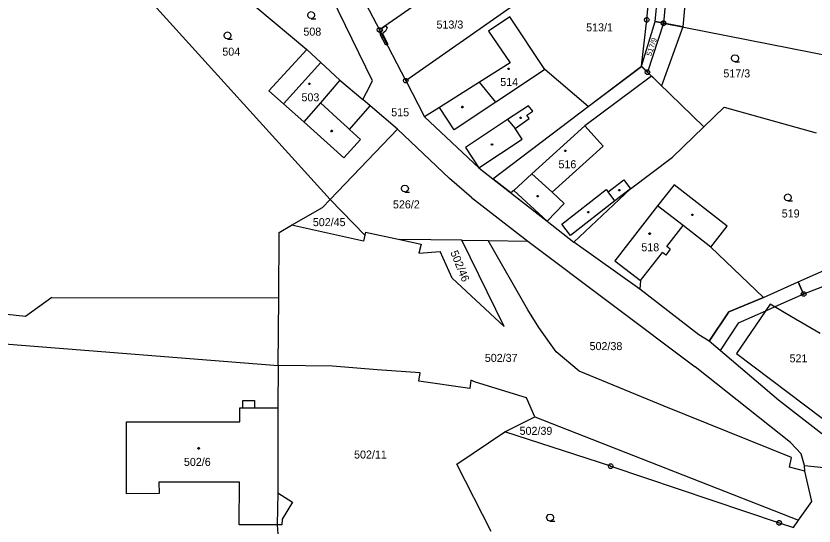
# Model space of a CAD drawing. Extents: x -759060 to -757386, y -1172273 to -1170948.
# Drawn here: x -758782.5 to -758613.1, y -1171856.8 to -1171748.6 of the extents above; entities that cross this region are included whole.
import ezdxf

# ---------------------------------------------------------------- set-up
doc = ezdxf.new("R2010")
doc.units = 0
for name, color, linetype in [('Vrstva 1', 7, 'Continuous'), ('Vrstva 12', 7, 'Continuous'), ('Vrstva 13', 7, 'Continuous'), ('Vrstva 2', 7, 'Continuous'), ('Vrstva 3', 7, 'Continuous'), ('Vrstva 4', 7, 'Continuous'), ('Vrstva 5', 7, 'Continuous'), ('Vrstva 8', 7, 'Continuous')]:
    doc.layers.add(name, color=color, linetype=linetype)

msp = doc.modelspace()

# ---------------------------------------------------------------- linework, layer by layer
at = {"layer": 'Vrstva 1'}
for p, q in [((-758641.75, -1171713.64), (-758645.01, -1171750.08)), ((-758646.79, -1171749.73), (-758644.64, -1171725.81)), ((-758715.81, -1171787.49), (-758770.24, -1171727.37)), ((-758648.57, -1171749.38), (-758646.57, -1171727.16)), ((-758679.1, -1171733.19), (-758705.32, -1171751.52)), ((-758706.83, -1171762.29), (-758717.2, -1171740.92)), ((-758710.93, -1171740.72), (-758705.32, -1171751.52)), ((-758699.75, -1171762.27), (-758676.85, -1171746.26)), ((-758731.61, -1171746.63), (-758720.72, -1171755.65)), ((-758677.64, -1171748.72), (-758682.16, -1171751.77)), ((-758670.25, -1171759.94), (-758677.64, -1171748.72)), ((-758649.72, -1171759.23), (-758648.57, -1171749.38)), ((-758649.72, -1171759.23), (-758646.79, -1171749.73)), ((-758645.01, -1171750.08), (-758646.79, -1171749.73)), ((-758645.01, -1171750.08), (-758648.43, -1171760.48)), ((-758645.01, -1171750.08), (-758607.53, -1171757.49)), ((-758699.75, -1171762.27), (-758705.32, -1171751.52)), ((-758682.16, -1171751.77), (-758677.59, -1171758.48)), ((-758720.72, -1171755.65), (-758728.8, -1171764.43)), ((-758720.72, -1171755.65), (-758717.76, -1171758.42)), ((-758717.76, -1171758.42), (-758713.73, -1171762.16)), ((-758677.59, -1171758.48), (-758684.12, -1171762.6)), ((-758661, -1171767.77), (-758670.25, -1171759.94)), ((-758661, -1171767.77), (-758649.72, -1171759.23)), ((-758648.43, -1171760.48), (-758649.72, -1171759.23)), ((-758648.43, -1171760.48), (-758636.47, -1171772.09)), ((-758713.73, -1171762.16), (-758708.87, -1171766.3)), ((-758708.11, -1171764.8), (-758706.83, -1171762.29)), ((-758699.75, -1171762.27), (-758695.75, -1171769.98)), ((-758684.12, -1171762.6), (-758692.61, -1171767.95)), ((-758728.8, -1171764.43), (-758725.68, -1171767.22)), ((-758708.87, -1171766.3), (-758708.11, -1171764.8)), ((-758707.34, -1171767.6), (-758708.87, -1171766.3)), ((-758725.68, -1171767.22), (-758721.42, -1171771.03)), ((-758711.71, -1171772.63), (-758707.34, -1171767.6)), ((-758701.5, -1171772.58), (-758707.34, -1171767.6)), ((-758692.61, -1171767.95), (-758695.75, -1171769.98)), ((-758681.28, -1171783.12), (-758661, -1171767.77)), ((-758636.47, -1171772.09), (-758632.15, -1171767.9)), ((-758632.15, -1171767.9), (-758612.62, -1171773.32)), ((-758695.75, -1171769.98), (-758684.25, -1171780.75)), ((-758721.42, -1171771.03), (-758712.88, -1171778.67)), ((-758715.81, -1171787.49), (-758701.5, -1171772.58)), ((-758709.36, -1171774.77), (-758711.71, -1171772.63)), ((-758690.44, -1171783.03), (-758701.5, -1171772.58)), ((-758643.09, -1171778.53), (-758636.47, -1171772.09)), ((-758712.88, -1171778.67), (-758709.36, -1171774.77)), ((-758652.04, -1171785.22), (-758643.09, -1171778.53)), ((-758684.25, -1171780.75), (-758681.28, -1171783.12)), ((-758685.82, -1171787.05), (-758690.44, -1171783.03)), ((-758681.28, -1171783.12), (-758669.72, -1171792.08)), ((-758664.06, -1171796.53), (-758652.04, -1171785.22)), ((-758642.78, -1171784.38), (-758646.26, -1171788.84)), ((-758631.52, -1171793.17), (-758642.78, -1171784.38)), ((-758685.82, -1171787.05), (-758673.86, -1171796.32)), ((-758717.42, -1171789.19), (-758715.81, -1171787.49)), ((-758715.81, -1171787.49), (-758708.45, -1171795.04)), ((-758616.41, -1171804.96), (-758576.87, -1171787.26)), ((-758723.99, -1171792.98), (-758717.42, -1171789.19)), ((-758646.26, -1171788.84), (-758655.37, -1171800.5)), ((-758669.72, -1171792.08), (-758664.06, -1171796.53)), ((-758726.61, -1171794.49), (-758723.99, -1171792.98)), ((-758708.75, -1171796.32), (-758723.99, -1171792.98)), ((-758634.97, -1171797.63), (-758631.52, -1171793.17)), ((-758726.73, -1171808.34), (-758726.61, -1171794.49)), ((-758708.45, -1171795.04), (-758708.75, -1171796.32)), ((-758708.31, -1171794.43), (-758708.45, -1171795.04)), ((-758708.31, -1171794.43), (-758701.03, -1171796.01)), ((-758701.03, -1171796.01), (-758696.5, -1171797)), ((-758687.82, -1171796.16), (-758701.03, -1171796.01)), ((-758696.5, -1171797), (-758696.97, -1171798.9)), ((-758678.82, -1171814.43), (-758687.82, -1171796.16)), ((-758687.82, -1171796.16), (-758682.23, -1171796.23)), ((-758682.23, -1171796.23), (-758673.86, -1171796.32)), ((-758673.86, -1171810.89), (-758682.23, -1171796.23)), ((-758673.86, -1171796.32), (-758638.27, -1171823.05)), ((-758650.04, -1171806.5), (-758664.06, -1171796.53)), ((-758696.97, -1171798.9), (-758692.43, -1171798.56)), ((-758689.87, -1171804.18), (-758692.43, -1171798.56)), ((-758623.82, -1171808.27), (-758634.97, -1171797.63)), ((-758655.37, -1171800.5), (-758649.89, -1171804.72)), ((-758603.34, -1171802.93), (-758615.26, -1171807.57)), ((-758689.87, -1171804.18), (-758678.82, -1171814.43)), ((-758649.89, -1171804.72), (-758650.04, -1171806.5)), ((-758623.82, -1171808.27), (-758616.41, -1171804.96)), ((-758615.26, -1171807.57), (-758616.41, -1171804.96)), ((-758637.53, -1171816.21), (-758650.04, -1171806.5)), ((-758774.9, -1171808.33), (-758780.52, -1171812.32)), ((-758774.9, -1171808.33), (-758726.73, -1171808.34)), ((-758726.85, -1171822.75), (-758726.73, -1171808.34)), ((-758623.82, -1171808.27), (-758631.13, -1171811.33)), ((-758780.52, -1171812.32), (-758804.48, -1171809.81)), ((-758622.34, -1171809.71), (-758629.53, -1171820.16)), ((-758617.85, -1171812.39), (-758622.34, -1171809.71)), ((-758671.46, -1171814.7), (-758673.86, -1171810.89)), ((-758631.13, -1171811.33), (-758635.31, -1171817.56)), ((-758611.74, -1171815.92), (-758617.85, -1171812.39)), ((-758667.8, -1171819.81), (-758671.46, -1171814.7)), ((-758635.31, -1171817.56), (-758637.53, -1171816.21)), ((-758620.59, -1171830.09), (-758635.31, -1171817.56)), ((-758785.82, -1171818.1), (-758726.85, -1171822.75)), ((-758662.9, -1171823.92), (-758667.8, -1171819.81)), ((-758629.53, -1171820.16), (-758611.35, -1171833.94)), ((-758726.85, -1171822.75), (-758726.93, -1171831.7)), ((-758715.31, -1171822.87), (-758726.85, -1171822.75)), ((-758705.84, -1171823.68), (-758715.31, -1171822.87)), ((-758696.69, -1171824.32), (-758705.84, -1171823.68)), ((-758696.97, -1171826.08), (-758696.69, -1171824.32)), ((-758644.87, -1171831.38), (-758662.9, -1171823.92)), ((-758618.04, -1171839.11), (-758638.27, -1171823.05)), ((-758685.92, -1171825.84), (-758686.17, -1171827.61)), ((-758684.96, -1171826.27), (-758685.92, -1171825.84)), ((-758686.17, -1171827.61), (-758696.97, -1171826.08)), ((-758674.08, -1171829.6), (-758684.96, -1171826.27)), ((-758734.34, -1171831.71), (-758734.34, -1171830.18)), ((-758734.34, -1171830.18), (-758731.85, -1171830.18)), ((-758731.85, -1171830.18), (-758731.84, -1171831.7)), ((-758672.35, -1171833.62), (-758674.08, -1171829.6)), ((-758611.37, -1171837.24), (-758620.59, -1171830.09)), ((-758735, -1171834.72), (-758735, -1171831.71)), ((-758735, -1171831.71), (-758734.34, -1171831.71)), ((-758731.84, -1171831.7), (-758726.93, -1171831.7)), ((-758726.93, -1171831.7), (-758726.93, -1171849.78)), ((-758617.82, -1171842.28), (-758644.87, -1171831.38)), ((-758678.68, -1171836.78), (-758672.35, -1171833.62)), ((-758672.35, -1171833.62), (-758616.32, -1171855.59)), ((-758759.04, -1171849.97), (-758759.04, -1171834.72)), ((-758759.04, -1171834.72), (-758735, -1171834.72)), ((-758688.87, -1171843.64), (-758678.68, -1171836.78)), ((-758656.22, -1171844.11), (-758678.68, -1171836.78)), ((-758615.81, -1171841.5), (-758618.04, -1171839.11)), ((-758618.25, -1171844.29), (-758617.82, -1171842.28)), ((-758615.05, -1171843.99), (-758615.81, -1171841.5)), ((-758681.63, -1171857.97), (-758688.87, -1171843.64)), ((-758656.22, -1171844.11), (-758620.44, -1171856.14)), ((-758615.04, -1171845.17), (-758618.25, -1171844.29)), ((-758615.04, -1171845.17), (-758615.05, -1171843.99)), ((-758615.05, -1171843.99), (-758610.96, -1171844.36)), ((-758613.49, -1171851.58), (-758615.04, -1171845.17)), ((-758735.04, -1171847.51), (-758752.16, -1171847.48)), ((-758752.16, -1171847.48), (-758752.13, -1171849.9)), ((-758735.1, -1171856.53), (-758735.04, -1171847.51)), ((-758726.93, -1171849.78), (-758723.83, -1171851.74)), ((-758752.13, -1171849.9), (-758759.04, -1171849.97)), ((-758723.83, -1171851.74), (-758726.01, -1171855.37)), ((-758616.32, -1171855.59), (-758613.49, -1171851.58)), ((-758727.06, -1171856.58), (-758735.1, -1171856.53)), ((-758726.03, -1171856.52), (-758727.06, -1171856.58)), ((-758726.01, -1171855.37), (-758726.03, -1171856.52)), ((-758620.44, -1171856.14), (-758617.44, -1171857.11)), ((-758617.44, -1171857.11), (-758616.32, -1171855.59)), ((-758727.06, -1171856.58), (-758726.92, -1171858.5))]:
    msp.add_line(p, q, dxfattribs=at)
at = {"layer": 'Vrstva 12'}
for p, q in [((-758677.64, -1171748.72), (-758682.16, -1171751.77)), ((-758670.25, -1171759.94), (-758677.64, -1171748.72)), ((-758682.16, -1171751.77), (-758677.59, -1171758.48)), ((-758717.76, -1171758.42), (-758725.68, -1171767.22)), ((-758717.76, -1171758.42), (-758713.73, -1171762.16)), ((-758677.59, -1171758.48), (-758684.12, -1171762.6)), ((-758670.25, -1171759.94), (-758674.35, -1171762.67)), ((-758713.73, -1171762.16), (-758717.88, -1171766.98)), ((-758680.6, -1171766.82), (-758684.12, -1171762.6)), ((-758674.35, -1171762.67), (-758680.6, -1171766.82)), ((-758725.68, -1171767.22), (-758721.42, -1171771.03)), ((-758717.88, -1171766.98), (-758721.42, -1171771.03)), ((-758672.95, -1171782.04), (-758661.75, -1171771.84)), ((-758661.75, -1171771.84), (-758657.85, -1171776.16)), ((-758657.85, -1171776.16), (-758668.68, -1171785.93)), ((-758672.95, -1171782.04), (-758668.68, -1171785.93)), ((-758646.26, -1171788.84), (-758655.37, -1171800.5)), ((-758640.81, -1171793.01), (-758646.26, -1171788.84)), ((-758644.29, -1171797.5), (-758640.81, -1171793.01)), ((-758649.89, -1171804.72), (-758645.25, -1171798.73)), ((-758644.54, -1171799.29), (-758645.25, -1171798.73)), ((-758643.58, -1171798.05), (-758644.54, -1171799.29)), ((-758643.58, -1171798.05), (-758644.29, -1171797.5)), ((-758655.37, -1171800.5), (-758649.89, -1171804.72)), ((-758735, -1171834.72), (-758735, -1171831.71)), ((-758735, -1171831.71), (-758734.34, -1171831.71)), ((-758734.34, -1171831.71), (-758731.84, -1171831.7)), ((-758731.84, -1171831.7), (-758726.93, -1171831.7)), ((-758726.93, -1171831.7), (-758726.93, -1171849.78)), ((-758759.04, -1171849.97), (-758759.04, -1171834.72)), ((-758759.04, -1171834.72), (-758735, -1171834.72)), ((-758735.04, -1171847.51), (-758752.16, -1171847.48)), ((-758752.16, -1171847.48), (-758752.13, -1171849.9)), ((-758735.1, -1171856.53), (-758735.04, -1171847.51)), ((-758726.93, -1171849.78), (-758727.06, -1171856.58)), ((-758752.13, -1171849.9), (-758759.04, -1171849.97)), ((-758727.06, -1171856.58), (-758735.1, -1171856.53))]:
    msp.add_line(p, q, dxfattribs=at)
at = {"layer": 'Vrstva 13'}
for p, q in [((-758637.64, -1171714.46), (-758640.9, -1171750.89)), ((-758646.79, -1171749.73), (-758644.64, -1171725.81)), ((-758649.72, -1171759.23), (-758646.79, -1171749.73)), ((-758640.9, -1171750.89), (-758646.79, -1171749.73)), ((-758646.79, -1171749.73), (-758640.9, -1171750.89)), ((-758704.88, -1171751.21), (-758704.06, -1171750.64)), ((-758704.61, -1171751.59), (-758704.88, -1171751.21)), ((-758704.06, -1171750.64), (-758703.73, -1171751.1)), ((-758703.73, -1171751.1), (-758704.02, -1171751.81)), ((-758640.9, -1171750.89), (-758645.41, -1171763.41)), ((-758705.21, -1171751.98), (-758705.11, -1171751.92)), ((-758705.09, -1171752.63), (-758705.21, -1171751.98)), ((-758705.11, -1171751.92), (-758704.61, -1171751.59)), ((-758703.72, -1171754.61), (-758705.11, -1171751.92)), ((-758705.11, -1171751.92), (-758703.72, -1171754.61)), ((-758704.01, -1171754.76), (-758705.09, -1171752.63)), ((-758704.02, -1171751.81), (-758704.65, -1171752.22)), ((-758704.65, -1171752.22), (-758704.59, -1171752.51)), ((-758704.59, -1171752.51), (-758703.56, -1171754.53)), ((-758703.72, -1171754.61), (-758704.01, -1171754.76)), ((-758703.56, -1171754.53), (-758703.72, -1171754.61)), ((-758661, -1171767.77), (-758649.7, -1171759.25)), ((-758645.41, -1171763.41), (-758649.72, -1171759.23)), ((-758649.7, -1171759.25), (-758647.54, -1171761.33)), ((-758647.54, -1171761.33), (-758661.75, -1171771.84)), ((-758681.28, -1171783.12), (-758661, -1171767.77)), ((-758661.75, -1171771.84), (-758672.95, -1171782.04)), ((-758677.41, -1171786.12), (-758681.28, -1171783.12)), ((-758672.95, -1171782.04), (-758676.82, -1171785.57)), ((-758676.82, -1171785.57), (-758677.41, -1171786.12)), ((-758623.82, -1171808.27), (-758616.41, -1171804.96)), ((-758616.41, -1171804.96), (-758615.26, -1171807.57)), ((-758631.13, -1171811.33), (-758623.82, -1171808.27)), ((-758615.26, -1171807.57), (-758621.37, -1171810.29)), ((-758621.37, -1171810.29), (-758623.34, -1171811.17)), ((-758635.31, -1171817.56), (-758631.13, -1171811.33)), ((-758623.34, -1171811.17), (-758629.15, -1171813.75)), ((-758629.15, -1171813.75), (-758633.01, -1171819.52)), ((-758633.01, -1171819.52), (-758635.31, -1171817.56))]:
    msp.add_line(p, q, dxfattribs=at)
at = {"layer": 'Vrstva 3'}
for points in [[(-758719.82, -1171749.11), (-758720.2, -1171749.01), (-758720.47, -1171748.74), (-758720.57, -1171748.37), (-758720.47, -1171748), (-758720.2, -1171747.73), (-758719.83, -1171747.63), (-758719.46, -1171747.73), (-758719.19, -1171748), (-758719.09, -1171748.38), (-758719.19, -1171748.76), (-758719.46, -1171749.03), (-758719.84, -1171749.13), (-758718.84, -1171749.13)], [(-758737.59, -1171753.42), (-758737.97, -1171753.32), (-758738.24, -1171753.05), (-758738.34, -1171752.68), (-758738.24, -1171752.31), (-758737.97, -1171752.04), (-758737.6, -1171751.94), (-758737.23, -1171752.04), (-758736.96, -1171752.31), (-758736.86, -1171752.69), (-758736.96, -1171753.07), (-758737.23, -1171753.34), (-758737.61, -1171753.44), (-758736.61, -1171753.44)], [(-758629.83, -1171758.26), (-758630.21, -1171758.16), (-758630.48, -1171757.89), (-758630.58, -1171757.52), (-758630.48, -1171757.15), (-758630.21, -1171756.88), (-758629.84, -1171756.78), (-758629.47, -1171756.88), (-758629.2, -1171757.15), (-758629.1, -1171757.53), (-758629.2, -1171757.91), (-758629.47, -1171758.18), (-758629.85, -1171758.28), (-758628.85, -1171758.28)], [(-758699.92, -1171785.91), (-758700.3, -1171785.81), (-758700.57, -1171785.54), (-758700.67, -1171785.17), (-758700.57, -1171784.8), (-758700.3, -1171784.53), (-758699.93, -1171784.43), (-758699.56, -1171784.53), (-758699.29, -1171784.8), (-758699.19, -1171785.18), (-758699.29, -1171785.56), (-758699.56, -1171785.83), (-758699.94, -1171785.93), (-758698.94, -1171785.93)], [(-758618.61, -1171787.8), (-758618.99, -1171787.7), (-758619.26, -1171787.43), (-758619.36, -1171787.06), (-758619.26, -1171786.69), (-758618.99, -1171786.42), (-758618.62, -1171786.32), (-758618.25, -1171786.42), (-758617.98, -1171786.69), (-758617.88, -1171787.07), (-758617.98, -1171787.45), (-758618.25, -1171787.72), (-758618.63, -1171787.82), (-758617.63, -1171787.82)], [(-758669.1, -1171855.74), (-758669.48, -1171855.64), (-758669.75, -1171855.37), (-758669.85, -1171855), (-758669.75, -1171854.63), (-758669.48, -1171854.36), (-758669.11, -1171854.26), (-758668.74, -1171854.36), (-758668.47, -1171854.63), (-758668.37, -1171855.01), (-758668.47, -1171855.39), (-758668.74, -1171855.66), (-758669.12, -1171855.76), (-758668.12, -1171855.76)]]:
    msp.add_lwpolyline(points, dxfattribs=at)
at = {"layer": 'Vrstva 4'}
for p, q in [((-758717.76, -1171758.42), (-758725.68, -1171767.22)), ((-758670.25, -1171759.94), (-758674.35, -1171762.67)), ((-758713.73, -1171762.16), (-758717.88, -1171766.98)), ((-758680.6, -1171766.82), (-758684.12, -1171762.6)), ((-758674.35, -1171762.67), (-758680.6, -1171766.82)), ((-758717.88, -1171766.98), (-758721.42, -1171771.03)), ((-758717.88, -1171766.98), (-758713.56, -1171770.93)), ((-758689.49, -1171772.73), (-758692.61, -1171767.95)), ((-758680.6, -1171766.82), (-758689.49, -1171772.73)), ((-758673.65, -1171767.62), (-758678.11, -1171770.5)), ((-758672.8, -1171768.72), (-758673.65, -1171767.62)), ((-758674.01, -1171769.62), (-758672.8, -1171768.72)), ((-758673.52, -1171770.34), (-758674.01, -1171769.62)), ((-758713.56, -1171770.93), (-758712.14, -1171772.23)), ((-758678.11, -1171770.5), (-758687.07, -1171776.44)), ((-758678.11, -1171770.5), (-758676.51, -1171772.4)), ((-758676.51, -1171772.4), (-758673.52, -1171770.34)), ((-758672.95, -1171782.04), (-758661.75, -1171771.84)), ((-758661.75, -1171771.84), (-758657.85, -1171776.16)), ((-758712.14, -1171772.23), (-758711.71, -1171772.63)), ((-758675.01, -1171774.68), (-758676.51, -1171772.4)), ((-758684.25, -1171780.75), (-758675.01, -1171774.68)), ((-758687.07, -1171776.44), (-758684.25, -1171780.75)), ((-758657.85, -1171776.16), (-758668.68, -1171785.93)), ((-758676.82, -1171785.57), (-758672.95, -1171782.04)), ((-758672.95, -1171782.04), (-758668.68, -1171785.93)), ((-758656.79, -1171785.85), (-758653.46, -1171783.31)), ((-758653.46, -1171783.31), (-758652.04, -1171785.22)), ((-758666.62, -1171792.76), (-758657.19, -1171785.35)), ((-758657.19, -1171785.35), (-758656.79, -1171785.85)), ((-758652.04, -1171785.22), (-758655.32, -1171787.78)), ((-758669.72, -1171792.08), (-758676.82, -1171785.57)), ((-758668.68, -1171785.93), (-758666.13, -1171788.35)), ((-758655.32, -1171787.78), (-758656.79, -1171785.85)), ((-758666.13, -1171788.35), (-758669.72, -1171792.08)), ((-758655.32, -1171787.78), (-758664.75, -1171795.12)), ((-758640.81, -1171793.01), (-758646.26, -1171788.84)), ((-758664.75, -1171795.12), (-758666.62, -1171792.76)), ((-758644.29, -1171797.5), (-758640.81, -1171793.01)), ((-758634.97, -1171797.63), (-758640.81, -1171793.01)), ((-758649.89, -1171804.72), (-758645.25, -1171798.73)), ((-758644.54, -1171799.29), (-758645.25, -1171798.73)), ((-758643.58, -1171798.05), (-758644.54, -1171799.29)), ((-758643.58, -1171798.05), (-758644.29, -1171797.5)), ((-758734.34, -1171831.71), (-758731.84, -1171831.7)), ((-758726.93, -1171849.78), (-758727.06, -1171856.58))]:
    msp.add_line(p, q, dxfattribs=at)
at = {"layer": 'Vrstva 5'}
for points in [[(-758677.83, -1171759.64), (-758677.74, -1171759.79), (-758677.83, -1171759.94), (-758678.01, -1171759.94), (-758678.1, -1171759.79), (-758678.01, -1171759.64)], [(-758720.11, -1171762.83), (-758720.02, -1171762.98), (-758720.11, -1171763.13), (-758720.29, -1171763.13), (-758720.38, -1171762.98), (-758720.29, -1171762.83)], [(-758687.62, -1171767.72), (-758687.53, -1171767.87), (-758687.62, -1171768.02), (-758687.8, -1171768.02), (-758687.89, -1171767.87), (-758687.8, -1171767.72)], [(-758675.28, -1171770.02), (-758675.19, -1171770.17), (-758675.28, -1171770.32), (-758675.46, -1171770.32), (-758675.55, -1171770.17), (-758675.46, -1171770.02)], [(-758715.36, -1171772.81), (-758715.27, -1171772.96), (-758715.36, -1171773.11), (-758715.54, -1171773.11), (-758715.63, -1171772.96), (-758715.54, -1171772.81)], [(-758681.35, -1171775.69), (-758681.26, -1171775.84), (-758681.35, -1171775.99), (-758681.53, -1171775.99), (-758681.62, -1171775.84), (-758681.53, -1171775.69)], [(-758665.77, -1171777.02), (-758665.68, -1171777.17), (-758665.77, -1171777.32), (-758665.95, -1171777.32), (-758666.04, -1171777.17), (-758665.95, -1171777.02)], [(-758654.29, -1171785.35), (-758654.2, -1171785.5), (-758654.29, -1171785.65), (-758654.47, -1171785.65), (-758654.56, -1171785.5), (-758654.47, -1171785.35)], [(-758671.66, -1171786.62), (-758671.57, -1171786.77), (-758671.66, -1171786.92), (-758671.84, -1171786.92), (-758671.93, -1171786.77), (-758671.84, -1171786.62)], [(-758660.92, -1171790.04), (-758660.83, -1171790.19), (-758660.92, -1171790.34), (-758661.1, -1171790.34), (-758661.19, -1171790.19), (-758661.1, -1171790.04)], [(-758638.82, -1171790.62), (-758638.73, -1171790.77), (-758638.82, -1171790.92), (-758639, -1171790.92), (-758639.09, -1171790.77), (-758639, -1171790.62)], [(-758647.87, -1171794.6), (-758647.78, -1171794.75), (-758647.87, -1171794.9), (-758648.05, -1171794.9), (-758648.14, -1171794.75), (-758648.05, -1171794.6)], [(-758743.62, -1171840.16), (-758743.53, -1171840.31), (-758743.62, -1171840.46), (-758743.8, -1171840.46), (-758743.89, -1171840.31), (-758743.8, -1171840.16)]]:
    msp.add_lwpolyline(points, close=True, dxfattribs=at)
at = {"layer": 'Vrstva 8'}
for p, q in [((-758648.69, -1171749.38), (-758648.45, -1171749.38)), ((-758645.13, -1171750.08), (-758644.89, -1171750.08)), ((-758705.44, -1171751.52), (-758705.2, -1171751.52)), ((-758648.55, -1171760.48), (-758648.31, -1171760.48)), ((-758699.87, -1171762.27), (-758699.63, -1171762.27)), ((-758615.38, -1171807.57), (-758615.14, -1171807.57)), ((-758656.34, -1171844.11), (-758656.1, -1171844.11)), ((-758620.56, -1171856.14), (-758620.32, -1171856.14))]:
    msp.add_line(p, q, dxfattribs=at)
for points in [[(-758648.42, -1171748.9), (-758648.17, -1171749.08), (-758648.07, -1171749.37), (-758648.17, -1171749.66), (-758648.42, -1171749.84), (-758648.73, -1171749.84), (-758648.98, -1171749.66), (-758649.08, -1171749.37), (-758648.98, -1171749.08), (-758648.73, -1171748.9)], [(-758644.86, -1171749.6), (-758644.61, -1171749.78), (-758644.51, -1171750.07), (-758644.61, -1171750.36), (-758644.86, -1171750.54), (-758645.17, -1171750.54), (-758645.42, -1171750.36), (-758645.52, -1171750.07), (-758645.42, -1171749.78), (-758645.17, -1171749.6)], [(-758705.17, -1171751.04), (-758704.92, -1171751.22), (-758704.82, -1171751.51), (-758704.92, -1171751.8), (-758705.17, -1171751.98), (-758705.48, -1171751.98), (-758705.73, -1171751.8), (-758705.83, -1171751.51), (-758705.73, -1171751.22), (-758705.48, -1171751.04)], [(-758648.28, -1171760), (-758648.03, -1171760.18), (-758647.93, -1171760.47), (-758648.03, -1171760.76), (-758648.28, -1171760.94), (-758648.59, -1171760.94), (-758648.84, -1171760.76), (-758648.94, -1171760.47), (-758648.84, -1171760.18), (-758648.59, -1171760)], [(-758699.6, -1171761.79), (-758699.35, -1171761.97), (-758699.25, -1171762.26), (-758699.35, -1171762.55), (-758699.6, -1171762.73), (-758699.91, -1171762.73), (-758700.16, -1171762.55), (-758700.26, -1171762.26), (-758700.16, -1171761.97), (-758699.91, -1171761.79)], [(-758615.11, -1171807.09), (-758614.86, -1171807.27), (-758614.76, -1171807.56), (-758614.86, -1171807.85), (-758615.11, -1171808.03), (-758615.42, -1171808.03), (-758615.67, -1171807.85), (-758615.77, -1171807.56), (-758615.67, -1171807.27), (-758615.42, -1171807.09)], [(-758656.07, -1171843.63), (-758655.82, -1171843.81), (-758655.72, -1171844.1), (-758655.82, -1171844.39), (-758656.07, -1171844.57), (-758656.38, -1171844.57), (-758656.63, -1171844.39), (-758656.73, -1171844.1), (-758656.63, -1171843.81), (-758656.38, -1171843.63)], [(-758620.29, -1171855.66), (-758620.04, -1171855.84), (-758619.94, -1171856.13), (-758620.04, -1171856.42), (-758620.29, -1171856.6), (-758620.6, -1171856.6), (-758620.85, -1171856.42), (-758620.95, -1171856.13), (-758620.85, -1171855.84), (-758620.6, -1171855.66)]]:
    msp.add_lwpolyline(points, close=True, dxfattribs=at)

# ---------------------------------------------------------------- texts
at = {"layer": 'Vrstva 2'}
for s, p in [('513/3', (-758693.223, -1171751.22)), ('508', (-758721.483, -1171752.73)), ('513/1', (-758661.443, -1171751.82)), ('504', (-758738.693, -1171756.97)), ('517/3', (-758632.303, -1171761.59)), ('514', (-758679.683, -1171763.41)), ('503', (-758721.893, -1171766.66)), ('515', (-758702.833, -1171769.84)), ('516', (-758667.323, -1171780.87)), ('526/2', (-758702.463, -1171789.39)), ('519', (-758619.913, -1171791.32)), ('502/45', (-758719.483, -1171793.16)), ('518', (-758649.723, -1171798.49)), ('502/38', (-758660.713, -1171819.47)), ('502/37', (-758682.963, -1171821.97)), ('521', (-758618.257, -1171822.06)), ('502/39', (-758675.573, -1171837.45)), ('502/11', (-758710.723, -1171842.48)), ('502/6', (-758746.853, -1171844.04))]:
    msp.add_text(s, height=1.7, dxfattribs=at).set_placement(p)
for s, height, rotation, p in [('517/9', 1.14, 71.79161, (-758647.608, -1171757.16)), ('502/46', 1.7, 292.20848, (-758690.33, -1171798.72))]:
    msp.add_text(s, height=height, rotation=rotation, dxfattribs=at).set_placement(p)

doc.saveas('drawing.dxf')
